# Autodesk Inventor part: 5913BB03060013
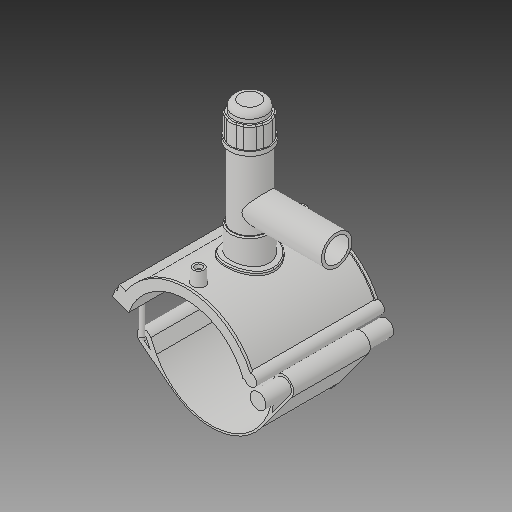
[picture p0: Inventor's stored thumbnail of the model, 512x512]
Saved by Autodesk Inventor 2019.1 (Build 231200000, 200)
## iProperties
Created: 2017-07
Part Number: 5913BB03060013
Material: Generic
Description: PLASSON HIGH VOLUME TAPPING TEE 6''IPS x 1 1/4''IPS
Document SubType Name: Modeling
Designer: KIM
Mass: 1712.7 g
Surface Area: 2671.49 cm^2
Volume: 1712.7 cm^3
Density: 1 g/cm^3
Appearance: Default
Author: KIM
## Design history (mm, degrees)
derived "5913B.ipt"
feature "Solid1::5913B.ipt"
feature "Solid2::5913B.ipt"
feature "Solid4::5913B.ipt"
feature "Solid5::5913B.ipt"
tag "TaggingFeature1"
body "Solid1"
body "Solid2"
other parameters: "d0" = 168, "d2" = 432.435, "d3" = 42, "d4" = 176.022, "d5" = 0, "d6" = 0.1, "d8" = 0, "d40" = 99.5904, "d41" = 67.2, "d43" = 0, "d45" = 0, "d47" = 201.3732, "d78" = 114, "d79" = 15, "d80" = 70.4088, "d82" = 5 deg, "d84" = 4, "d85" = 14, "d86" = 0, "d87" = 3, "d88" = 0, "d96" = 195.3504, "d97" = 3.52044, "d98" = 0, "d102" = 1.68, "d120" = 140 deg, "d121" = 24.228, "d122" = 20 deg, "d123" = 478.8, "d124" = 114.912, "d126" = 0, "d153" = 176.022, "d154" = 0, "d159" = 4.704, "d162" = 105.6132, "d163" = 0, "d164" = 84, "d169" = 4.0905, "d170" = 7.056, "d172" = 0, "d173" = 1, "d175" = 84, "d176" = 20 deg, "d177" = 11.76, "d178" = 23.52, "d180" = 0, "d183" = 9.408, "d184" = 9.408, "d187" = 95.76, "d188" = 7.056, "d189" = 11.76, "d190" = 0, "d191" = 143.64, "d193" = 6.048, "d194" = 3.024, "d195" = 90 deg, "d197" = 0, "d199" = 0, "d200" = 11.76, "d202" = 0, "d203" = 194.818, "d204" = 52.3488, "d205" = 38.5728, "d206" = 46.8384, "d207" = 146.1135, "d208" = 151.95804, "d209" = 181.18074, "d210" = 47.38944, "d211" = 55.104, "d212" = 44.0832, "d213" = 48.492, "d216" = 0, "d217" = 16.8, "d218" = 8.4, "d219" = 1.68, "d222" = 168, "d224" = 0, "d230" = 1.68, "d257" = 158.93, "d258" = 119.888, "d259" = 33.68, "d260" = 42.1, "d263" = 172.974, "d265" = 0, "d267" = 13.00006, "d268" = 2.60001, "d269" = 2.60001, "d271" = 2.60001, "d273" = 0, "d274" = 23.56194, "d275" = 134.4, "d277" = 67.2, "d278" = 268.8, "d280" = 0, "d281" = 168, "d283" = 0, "d285" = 0, "d290" = 16.8, "d291" = 21.84, "d293" = 92.4, "d294" = 86.52, "d296" = 25.2, "d297" = 20.16, "d_" = 168, "B_" = 172.974, "L_" = 176.022, "d_t" = 6, "H_2" = 194.818, "H_1" = 74.93, "d_1" = 42.1, "H_" = 119.888, "d1" = 191.52, "d192" = 6.048
